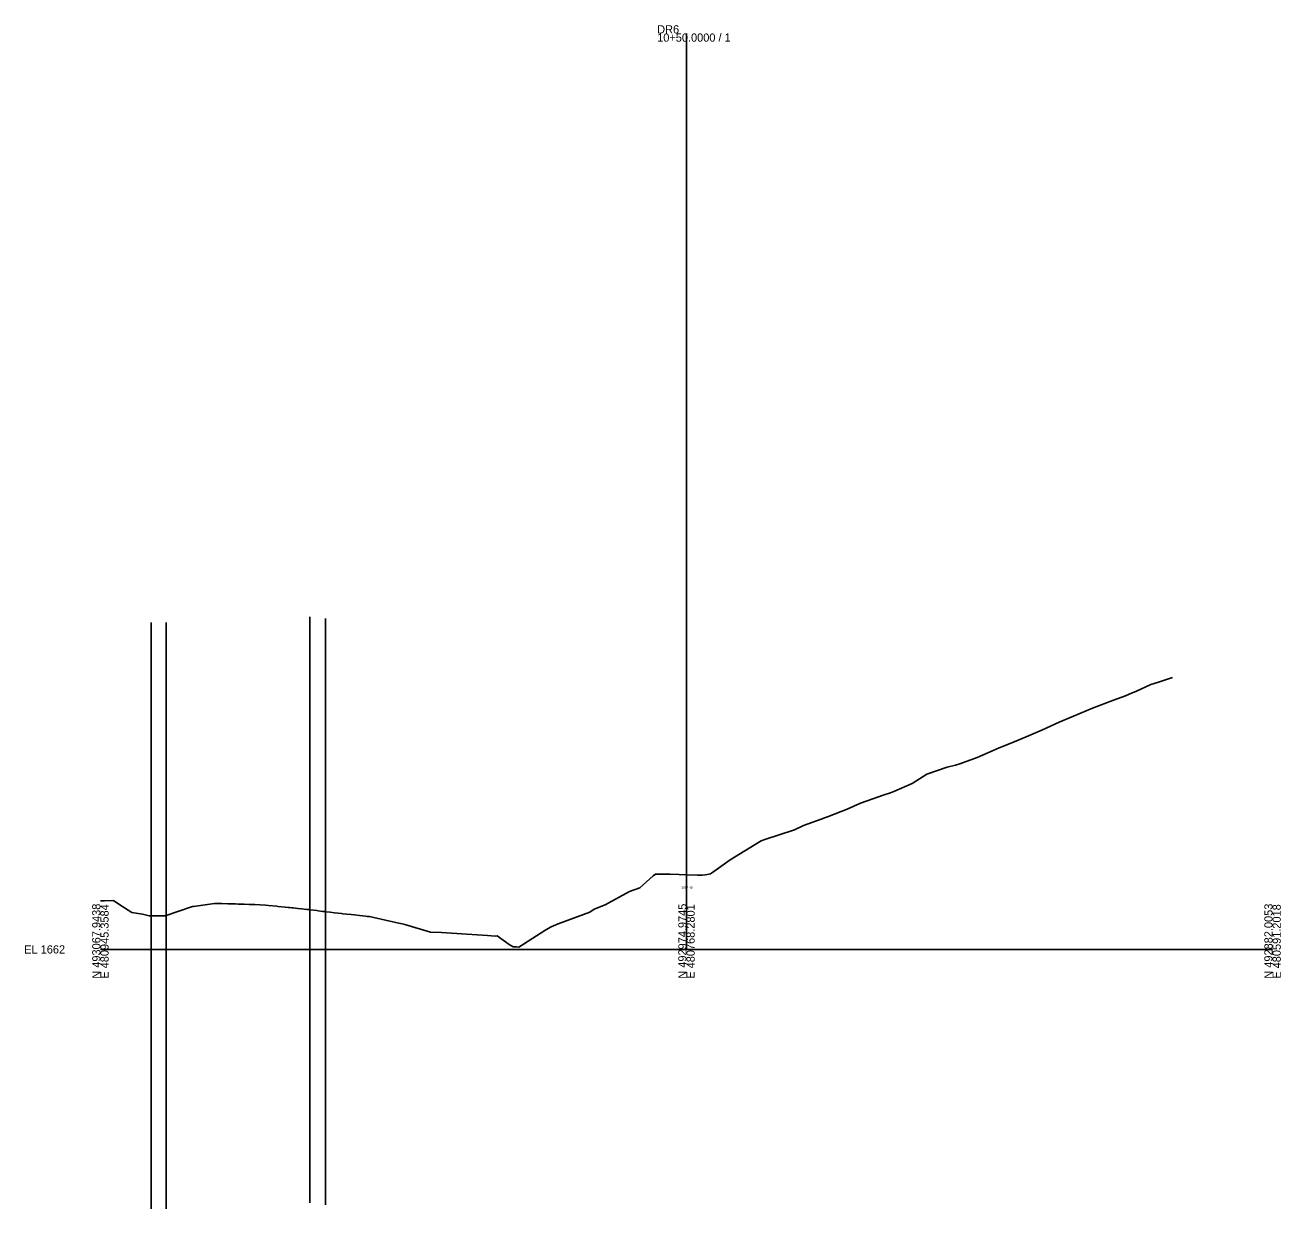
# Model space of a CAD drawing. Extents: x -26 to 403, y -88 to 5647.
# Drawn here: x -25.7 to 402.8, y 911.5 to 1315.3 of the extents above; entities that cross this region are included whole.
import ezdxf

# ---------------------------------------------------------------- set-up
doc = ezdxf.new("R2010")
doc.units = 0
for name, color, linetype in [('Exist Cross Section Cell', 7, 'Continuous'), ('Exist XS Center Line Elevation Label', 7, 'Continuous'), ('Exist XS Ground Line', 7, 'Continuous'), ('Scratch_Level_7', 7, 'Continuous')]:
    doc.layers.add(name, color=color, linetype=linetype)

msp = doc.modelspace()

# ---------------------------------------------------------------- linework, layer by layer
at = {"layer": 'Exist Cross Section Cell'}
for p, q in [((200, 1000), (200, 1312.48)), ((0, 1000), (200, 1000)), ((200, 1000), (400, 1000))]:
    msp.add_line(p, q, dxfattribs=at)
at = {"layer": 'Exist XS Ground Line'}
msp.add_lwpolyline([(0, 1016.61), (1.37, 1016.62), (4.47, 1016.63), (6.67, 1015.21), (10.74, 1012.54), (14.31, 1011.98), (16.63, 1011.46), (17.7, 1011.49), (22.12, 1011.42), (31.41, 1014.63), (31.76, 1014.69), (32.51, 1014.79), (38.93, 1015.69), (39.81, 1015.68), (40.45, 1015.67), (40.86, 1015.66), (41.45, 1015.65), (43.5, 1015.59), (46.05, 1015.51), (47.06, 1015.48), (49.03, 1015.41), (50.81, 1015.37), (52, 1015.33), (52.71, 1015.32), (54.53, 1015.21), (56.36, 1015.12), (57.34, 1015.02), (60.18, 1014.73), (60.64, 1014.68), (63.04, 1014.43), (64.09, 1014.32), (64.5, 1014.28), (65.37, 1014.19), (65.8, 1014.15), (67.41, 1013.99), (68.58, 1013.85), (70.48, 1013.63), (71.08, 1013.56), (71.4, 1013.52), (71.75, 1013.48), (73.9, 1013.22), (74.36, 1013.16), (75.82, 1012.98), (76.63, 1012.88), (77.05, 1012.83), (78.45, 1012.66), (79.91, 1012.49), (81.19, 1012.35), (82.22, 1012.24), (82.75, 1012.18), (84.12, 1012.03), (85.6, 1011.87), (86.76, 1011.75), (88.43, 1011.58), (90.45, 1011.35), (91.07, 1011.28), (91.45, 1011.24), (91.81, 1011.2), (101.28, 1009.12), (102.93, 1008.77), (103.84, 1008.5), (112.64, 1005.85), (116.44, 1005.74), (124.99, 1005.18), (132.13, 1004.74), (134.72, 1004.55), (135.43, 1004.66), (139.47, 1001.7), (140.85, 1000.86), (142, 1000.86), (142.84, 1000.8), (152.04, 1006.66), (153.79, 1007.7), (156.21, 1008.78), (167, 1012.76), (168.51, 1013.68), (172.26, 1015.26), (180.51, 1019.74), (184.04, 1021.04), (188.66, 1025.06), (189.48, 1025.64), (194.38, 1025.62), (197.47, 1025.58), (200, 1025.49), (203.78, 1025.37), (205.33, 1025.33), (206.34, 1025.48), (207.69, 1025.69), (208.18, 1025.77), (208.57, 1026.06), (214.87, 1030.52), (224.95, 1036.73), (225.54, 1037.03), (226.75, 1037.47), (236.84, 1040.76), (239.98, 1042.22), (245.96, 1044.43), (247.39, 1044.95), (248.13, 1045.26), (254.79, 1047.89), (259.43, 1049.88), (267.48, 1052.74), (269.61, 1053.42), (270.73, 1053.84), (277.02, 1056.6), (282.02, 1059.77), (289, 1062.18), (291.83, 1062.8), (293.32, 1063.33), (299.24, 1065.51), (304.62, 1067.83), (306.65, 1068.72), (310.51, 1070.3), (315.91, 1072.55), (321.46, 1074.93), (327.21, 1077.47), (332.03, 1079.62), (338.51, 1082.27), (345.67, 1085.01), (349.8, 1086.56), (351.09, 1087.05), (353.55, 1088.12), (358.5, 1090.32), (361.1, 1091.19), (365.91, 1092.73)], dxfattribs=at)
at = {"layer": 'Scratch_Level_7'}
for p, q in [((17.28, 1111.48), (17.28, 911.48)), ((22.49, 1111.55), (22.49, 911.55)), ((71.5, 1113.51), (71.5, 913.51)), ((76.79, 1112.86), (76.79, 912.86))]:
    msp.add_line(p, q, dxfattribs=at)

# ---------------------------------------------------------------- texts
at = {"layer": 'Exist Cross Section Cell'}
for s, p in [('10+50.0000 / 1', (190, 1309.68)), ('DR6', (190, 1312.48)), ('EL 1662', (-26, 998.6))]:
    msp.add_text(s, height=2.8, dxfattribs=at).set_placement(p)
for s, p in [('N 493067.9438', (0, 990)), ('E 480945.3584', (2.8, 990)), ('N 492974.9745', (200, 990)), ('E 480768.2801', (202.8, 990)), ('N 492882.0053', (400, 990)), ('E 480591.2018', (402.8, 990))]:
    msp.add_text(s, height=2.8, rotation=90, dxfattribs=at).set_placement(p)
at = {"layer": 'Exist XS Center Line Elevation Label'}
msp.add_text('1687.49', height=0.75, dxfattribs=at).set_placement((198.3, 1020.74))

doc.saveas('drawing.dxf')
